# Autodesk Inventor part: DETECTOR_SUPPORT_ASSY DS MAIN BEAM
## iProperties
Shininess: 64.0
Length Units: 11272
Angle Units: 11279
Time Units: 11290
Mass Units: 11286
Length Display Precision: 3
Angle Display Precision: 2
Compacted: True
Part Number: DETECTOR_SUPPORT_ASSY DS MAIN BEAM
Document SubType Name: Modeling
Created: 2004-08
Designer: John Blackburn
Material: MILD_STEEL
Manufacturer: Standard
Standards Organization: Custom
Density: 0.0
Volumn: 0.0
Area: 0.0
PropertySet Name: Model Information
Control State: 0
Master: False
Checked Out: False
Author: John Blackburn
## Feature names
1. ExtrusionMidplane1
2. ExtrusionThru1
3. ExtrusionThru2
4. ExtrusionThru3
5. ExtrusionThru4
6. ExtrusionThru5
7. ExtrusionThru6
8. ExtrusionThru7
